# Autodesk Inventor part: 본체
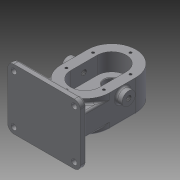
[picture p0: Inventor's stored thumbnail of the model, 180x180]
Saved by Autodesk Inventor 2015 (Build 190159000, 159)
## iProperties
Created: 2020-09
Part Number: 본체
Material: 일반
Document SubType Name: Modeling
Designer: Administrator
Density: 1 g/cm^3
Appearance: 기본값
Author: Administrator
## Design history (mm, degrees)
sketch "스케치1"
  geometry: L1 (0, 0)-(0, 44); L2 (0, 0)-(0, 44); L3 (40, 0)-(40, 44); L4 (-40, 44)-(-40, 0); A1 r 40 centre (0, 0) between (-40, 0) and (40, 0); A2 r 40 centre (0, 44) between (40, 44) and (-40, 44); 1 further point
  constraints: 10 end point, 4 point on circle, 4 tangent, 2 centre point, 2 vertical, 1 midpoint, 1 parallel
  dimensions: "d0" = 44 distance of L1.start L1.end; "d1" = 40 radius of A2
extrude "돌출1" new body sketch "스케치1" distance "d2" = 53; taper "d3" = 0 deg
sketch "스케치2"
  geometry: L1 (0, 0)-(0, 44); L2 (24, 0)-(24, 44); L3 (-24, 44)-(-24, 0); A1 r 24 centre (0, 0) between (-24, 0) and (24, 0); A2 r 24 centre (0, 44) between (24, 44) and (-24, 44); 1 further point
  constraints: 8 end point, 4 point on circle, 4 tangent, 2 centre point, 1 midpoint, 1 parallel, 1 vertical
  dimensions: "d4" = 44 distance of L1.start L1.end; "d5" = 24 radius of A2
extrude "돌출2" cut sketch "스케치2" distance "d6" = 29; taper "d7" = 0 deg
sketch "스케치3"
  geometry: L1 (0, 0)-(0, 44); C1 r 12.5 at (0, 44); C2 r 12.5 at (0, 0); 1 further point
  constraints: 3 coincident, 2 centre point, 2 end point, 1 vertical
  dimensions: "d9" = 44 distance of L1.start L1.end; "d10" = 25 diameter of C1; "d11" = 25 diameter of C2
extrude "돌출3" cut sketch "스케치3" distance "d12" = 15; taper "d13" = 0 deg
sketch "스케치4"
  geometry: C1 r 12.5 at (0, 0) reference; C2 r 8.5 at (0, 0); 1 further point
  constraints: 1 centre point, 1 coincident
  dimensions: "d14" = 17 diameter of C2
extrude "돌출4" cut sketch "스케치4" stored distance "d15" = 15; taper "d16" = 0 deg
sketch "스케치5"
  geometry: C1 r 8.5 at (0, 44) reference; C2 r 19 at (0, 44); 1 further point
  constraints: 1 centre point, 1 coincident
  dimensions: "d17" = 38 diameter of C2
extrude "돌출5" join sketch "스케치5" distance "d18" = 17; taper "d19" = 0 deg
sketch "스케치6"
  geometry: C1 r 19 at (0, 0) reference; C2 r 14 at (0, 0); 1 further point
  constraints: 1 centre point, 1 coincident
  dimensions: "d20" = 28 diameter of C2
extrude "돌출6" cut sketch "스케치6" distance "d21" = 7.3; taper "d22" = 0 deg
sketch "스케치7"
  geometry: L1 (0, 0)-(0, 44); L2 (0, 0)-(0, 44); L3 (31, 0)-(31, 44); L4 (-31, 44)-(-31, 0); L5 (0, 22)-(31, 22); L6 (31, 22)-(31, 44); L7 (31, 22)-(31, 0); L8 (0, 22)-(-31, 22); L9 (-31, 22)-(-31, 44); L10 (-31, 22)-(-31, 0); L11 (0, 22)-(0, 75); L12 (0, 22)-(0, -31); A1 r 31 centre (0, 0) between (-31, 0) and (31, 0); A2 r 31 centre (0, 44) between (31, 44) and (-31, 44)
  constraints: 26 end point, 6 point on circle, 5 tangent, 3 equal length, 3 midpoint, 2 centre point, 2 perpendicular, 2 vertical
  dimensions: "d23" = 44 distance of L1.start L1.end; "d24" = 62 diameter of A2
hole "구멍1" sketch "스케치7" at (0, 75), (-31, 44), (-31, 0), (31, 0), (31, 44), (0, -31) diameter "d25" = 4.134; stored, may be unused: countersink angle "d29" = 82 deg, drill point angle "d31" = 118 deg; dims "d26" = 10, "d27" = 3.023, "d28" = 2, "d30" = 12
node "작업 평면1"
sketch "스케치8"
  geometry: L1 (-19, -17)-(19, -17) reference; L2 (19, 0)-(19, -17) reference; L3 (0, -17)-(60, -17); L4 (60, -17)-(60, 83); L5 (60, 83)-(-60, 83); L6 (-60, 83)-(-60, -17); L7 (-60, -17)-(0, -17); 1 further point
  constraints: 10 end point, 2 perpendicular, 1 collinear, 1 horizontal, 1 midpoint, 1 point on line
  dimensions: "d33" = 60 distance of L3.start L3.end; "d34" = 100 distance of L3.end L4.end; "d35" = 120 distance of L4.end L5.end; "d36" = 100 distance of L5.end L6.end
extrude "돌출7" join sketch "스케치8" distance "d37" = 10; taper "d38" = 0 deg
node "작업 평면2"
sketch "스케치9"
  geometry: L1 (-60, -68)-(-60, -58) reference; L2 (60, -68)-(60, -58) reference; L3 (-60, -58)-(60, -58) reference; L4 (0, -58)-(-40, -58); L5 (-40, -58)-(-40, 0); L6 (0, -58)-(40, -58); L7 (40, -58)-(40, 0); A1 r 40 centre (0, 0) between (-40, 0) and (40, 0) reference; A2 r 40 centre (0, 0) between (-40, 0) and (40, 0); 1 further point
  constraints: 8 end point, 2 point on circle, 2 point on line, 1 centre point, 1 concentric, 1 midpoint
  dimensions: "d40" = 40 distance of L4.start L4.end; "d41" = 40 distance of L4.start L6.end
extrude "돌출8" join sketch "스케치9" stored distance "d42" = 37; taper "d43" = 0 deg
fillet "모깎기1" dims "d44" = 10
sketch "스케치13"
  geometry: C1 r 4.5 at (-50, -73); C2 r 4.5 at (-50, 7); C3 r 4.5 at (50, 7); C4 r 4.5 at (50, -73); A1 r 10 centre (-50, -73) between (-60, -73) and (-50, -83) reference; A2 r 10 centre (-50, 7) between (-50, 17) and (-60, 7) reference; A3 r 10 centre (50, 7) between (60, 7) and (50, 17) reference; A4 r 10 centre (50, -73) between (50, -83) and (60, -73) reference; 1 further point
  constraints: 4 centre point, 4 coincident
  dimensions: "d51" = 9 diameter of C1; "d52" = 9 diameter of C2; "d53" = 9 diameter of C3; "d54" = 9 diameter of C4
extrude "돌출10" cut sketch "스케치13" stored distance "d55" = 37; taper "d56" = 0 deg
sketch "스케치14"
  geometry: L1 (-73, -68)-(7, -68) reference; L2 (-53, 0)-(-53, 44) reference; L3 (0, 0)-(0, 44) reference; L4 (-53, 22)-(-39, 22); C1 r 11 at (-39, 22)
  constraints: 2 end point, 1 centre point, 1 coincident, 1 horizontal, 1 midpoint
  dimensions: "d57" = 14 distance of L4.start L4.end; "d58" = 22 diameter of C1
extrude "돌출11" join sketch "스케치14" distance "d59" = 10; taper "d60" = 0 deg
fillet "모깎기2" dims "d71" = 3
fillet "모깎기3" dims "d72" = 3
chamfer "모따기1" distance "d73" = 0.7; stored, may be unused: second distance "d74" = 2, angle "d75" = 30 deg
fillet "모깎기4" dims "d76" = 0.5
chamfer "모따기2" distance "d77" = 1; stored, may be unused: second distance "d78" = 2, angle "d79" = 30 deg
sketch "스케치19"
  geometry: C1 r 11 at (39, 22) reference; C2 r 11 at (39, 22); 1 further point
  constraints: 1 centre point, 1 coincident
  dimensions: "d80" = 22 diameter of C2
extrude "돌출13" join sketch "스케치19" distance "d81" = 10; taper "d82" = 0 deg
sketch "스케치20"
  geometry: C1 r 11 at (0, 0) reference; 1 further point
hole "구멍3" sketch "스케치20" at (0, 0) diameter "d83" = 8.376; stored, may be unused: countersink angle "d87" = 82 deg, drill point angle "d89" = 118 deg; dims "d84" = 27, "d85" = 3.023, "d86" = 2, "d88" = 34.3
sketch "스케치21"
  geometry: C1 r 11 at (0, 0) reference; 1 further point
hole "구멍4" sketch "스케치21" at (0, 0) diameter "d90" = 8.376; stored, may be unused: countersink angle "d94" = 82 deg, drill point angle "d96" = 118 deg; dims "d91" = 27, "d92" = 3.023, "d93" = 2, "d95" = 34.3
fillet "모깎기5" dims "d97" = 3
sketch "스케치22"
  geometry: L1 (-60, 7)-(-60, -73) reference; L2 (-50, -83)-(50, -83) reference; 2 further points
  constraints: 1 other
  dimensions: "d98" = 60 distance from line of point (0, -71) L1; "d99" = 12 distance from line of point (0, -71) L2
feature "엠보싱1" sketch "스케치22" dims "d9" = 44, "d10" = 25, "d11" = 25, "d100" = 0.5, "d101" = 0
fillet "모깎기6" dims "d102" = 3
node "솔리드1"
node "투영된 루프3"
other parameters: "d32" = -68, "d39" = 26.5
